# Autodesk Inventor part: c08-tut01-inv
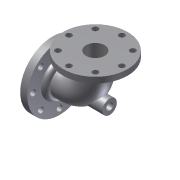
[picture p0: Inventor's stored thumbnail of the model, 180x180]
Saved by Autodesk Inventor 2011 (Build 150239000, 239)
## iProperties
Created: 2010-03
Part Number: c08-tut01-inv
Document SubType Name: Modeling
Designer: CADSoft
Density: 1 g/cm^3
Author: CADSoft
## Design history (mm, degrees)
sketch "Sketch1"
  geometry: 1 further point
sketch "Sketch2"
  geometry: L1 (-90, 35)-(-90, 0); L2 (0, -90)-(35, -90); A1 r 90 centre (0, 0) between (-90, 0) and (0, -90); 1 further point
  constraints: 4 end point, 2 point on circle, 2 tangent, 1 centre point, 1 coincident, 1 perpendicular, 1 vertical
  dimensions: "d0" = 35 distance of L1.start L1.end; "d1" = 35 distance of L2.start L2.end; "d2" = 90 radius of A1
workplane "Work Plane1"
sketch "Sketch3"
  geometry: C1 r 48.5 at (0, 0); 1 further point
  constraints: 1 centre point
  dimensions: "d3" = 97 diameter of C1
sweep "Sweep1" sketch "Sketch3" dims "d4" = 0
shell "Shell1" dims "d5" = 16
sketch "Sketch5"
  geometry: C1 r 32.5 at (0, 0) reference; C2 r 48.5 at (0, 0) reference; C3 r 32.5 at (0, 0); C4 r 112.5 at (0, 0); 1 further point
  constraints: 2 centre point, 2 coincident, 1 concentric
  dimensions: "d6" = 225 diameter of C4
extrude "Extrusion1" join sketch "Sketch5" distance "d7" = 20; taper "d8" = 0 deg
sketch "Sketch6"
  geometry: C1 r 32.5 at (0, 0) reference; C2 r 48.5 at (0, 0) reference; C3 r 32.5 at (0, 0); C4 r 112.5 at (0, 0); 1 further point
  constraints: 2 centre point, 2 coincident, 1 concentric
  dimensions: "d9" = 225 diameter of C4
extrude "Extrusion5" join sketch "Sketch6" distance "d21" = 25; taper "d22" = 0 deg
sketch "Sketch10"
  geometry: C1 r 48.5 at (0, 0) reference; C2 r 112.5 at (0, 0) reference; C3 r 64.5 at (0, 0); 1 further point
  constraints: 1 centre point, 1 coincident
  dimensions: "d23" = 129 diameter of C3
extrude "Extrusion6" join sketch "Sketch10" distance "d24" = 16; taper "d25" = 0 deg
fillet "Fillet3" dims "d26" = 16
workplane "Work Plane2"
sketch "Sketch11"
  geometry: L1 (-145, -112.5)-(-145, 112.5) reference; C1 r 25 at (0, 0); 1 further point
  constraints: 1 centre point
  dimensions: "d28" = 50 diameter of C1; "d29" = 145 distance from line of C1.centre L1
extrude "Extrusion7" join sketch "Sketch11" stored distance "d30" = 16; taper "d31" = 0 deg
hole "Hole1" diameter "d34" = 20; stored, may be unused: countersink angle "d38" = 90 deg, drill point angle "d40" = 0 deg; dims "d32" = 10, "d33" = 10, "d35" = 6, "d36" = 24, "d37" = 28, "d39" = 8
sketch "Sketch12"
  geometry: C1 r 32.5 at (0, 0) reference; 2 further points
  constraints: 1 horizontal alignment
  dimensions: "d41" = 92.5 distance of point (92.5, 0) C1.centre
hole "Hole2" sketch "Sketch12" at (92.5, 0) diameter "d42" = 20; stored, may be unused: countersink angle "d46" = 90 deg, drill point angle "d48" = 118 deg; dims "d43" = 6, "d44" = 24, "d45" = 28, "d47" = 2
pattern_circular "Circular Pattern1" dims angle "d50" = 360 deg
sketch "Sketch13"
  geometry: C1 r 48.5 at (0, 0) reference; 2 further points
  constraints: 1 horizontal alignment
  dimensions: "d52" = 92.5 distance of C1.centre point (-92.5, 0)
hole "Hole3" sketch "Sketch13" at (-92.5, 0) diameter "d53" = 20.5; stored, may be unused: countersink angle "d57" = 90 deg, drill point angle "d59" = 118 deg; dims "d54" = 6, "d55" = 24, "d56" = 28, "d58" = 2
pattern_circular "Circular Pattern2" dims angle "d61" = 360 deg
body "Solid1"
other parameters: "d27" = 175
